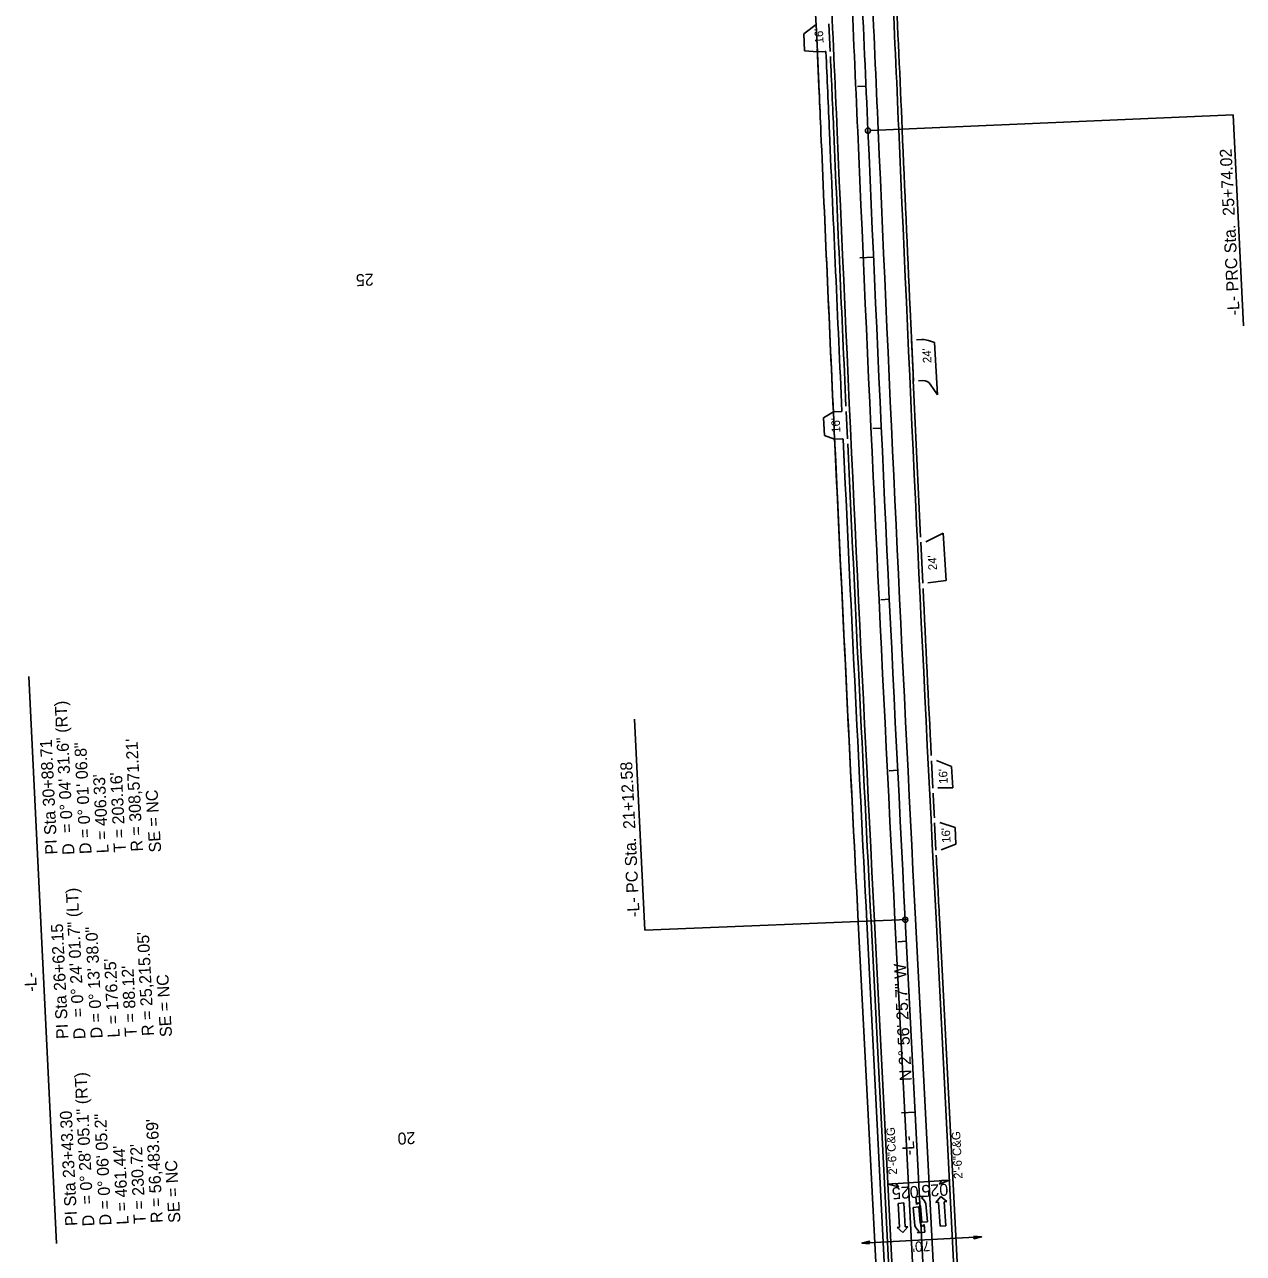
# Model space of a CAD drawing. Extents: x 2367848 to 2369479, y 800728 to 808616.
# Drawn here: x 2368386 to 2369098, y 802247 to 802965 of the extents above; entities that cross this region are included whole.
import ezdxf

# ---------------------------------------------------------------- set-up
doc = ezdxf.new("R2010")
doc.units = 0
for name, color, linetype in [('Prop Conc 2ft 6in Curb and Gutter', 7, 'Continuous'), ('Prop Conc 4in Sidewalk', 7, 'Continuous'), ('Prop Conc Drive Radius Type', 7, 'Continuous'), ('Prop Conc Driveway', 7, 'Continuous'), ('Prop Dimension', 7, 'Continuous'), ('Prop EOT', 7, 'Continuous'), ('Prop Horizontal Alignment', 7, 'Continuous'), ('Prop Horizontal Alignment Curve and Spiral Data', 7, 'Continuous'), ('Prop Horizontal Alignment Direction Label', 7, 'Continuous'), ('Prop Horizontal Alignment Station Label', 7, 'Continuous'), ('Prop Horizontal Alignment Tick Label', 7, 'Continuous'), ('Prop Horizontal Alignment Tick Large', 7, 'Continuous'), ('Prop Horizontal Alignment Tick Small', 7, 'Continuous'), ('Prop Lane Arrow CELL', 7, 'Continuous'), ('Prop Lane Lines', 7, 'Continuous'), ('Prop Shade Light', 7, 'Continuous'), ('Prop Superelevation  Arrow CELL', 7, 'Continuous'), ('Prop Superelevation Label', 7, 'Continuous'), ('Prop Terminator CELL', 7, 'Continuous')]:
    doc.layers.add(name, color=color, linetype=linetype)

msp = doc.modelspace()

# ---------------------------------------------------------------- linework, layer by layer
at = {"layer": 'Prop Conc 2ft 6in Curb and Gutter'}
for p, q in [((2368900.11, 802064.22), (2368880.75, 802441.11)), ((2368933.42, 802195.49), (2368920.7, 802443.16))]:
    msp.add_line(p, q, dxfattribs=at)
for centre, radius, start, end in [((2343687.36, 801815.32), 25235.05, 2.472411, 2.872893), ((2343687.36, 801815.32), 25195.05, 2.472411, 2.572986), ((2425310.05, 805339.67), 56503.69, 182.472411, 182.634937), ((2425310.05, 805339.67), 56463.69, 182.472411, 182.57923), ((2425310.05, 805339.67), 56463.69, 182.57923, 182.714413), ((2425310.05, 805339.67), 56503.69, 182.657207, 182.940485), ((2425310.05, 805339.67), 56463.69, 182.744855, 182.844086), ((2425310.05, 805339.67), 56463.69, 182.866413, 182.880976), ((2425310.05, 805339.67), 56463.69, 182.9033, 182.940485)]:
    msp.add_arc(centre, radius, start, end, dxfattribs=at)
at = {"layer": 'Prop Conc 4in Sidewalk'}
for p, q in [((2368892.58, 802064.58), (2368873.26, 802440.72)), ((2368897.6, 802064.34), (2368878.26, 802440.98))]:
    msp.add_line(p, q, dxfattribs=at)
for centre, radius, start, end in [((2343687.36, 801815.32), 25187.55, 2.614684, 2.872893), ((2343687.36, 801815.32), 25187.55, 2.472411, 2.583481), ((2368854, 802946.23), 3.01, 82.7914, 92.37863), ((2343687.36, 801815.32), 25192.55, 2.472411, 2.579707), ((2425310.05, 805339.67), 56511.19, 182.472411, 182.638782), ((2425310.05, 805339.67), 56506.19, 182.472411, 182.637937), ((2368863.1, 802741.94), 3, 272.68387, 282.26278), ((2425310.05, 805339.67), 56511.19, 182.652485, 182.940485), ((2368864.11, 802719.95), 3.01, 82.87062, 92.4209), ((2425108.22, 805329.81), 56304.12, 182.653736, 182.941)]:
    msp.add_arc(centre, radius, start, end, dxfattribs=at)
at = {"layer": 'Prop Conc Drive Radius Type'}
for p, q in [((2368856.87, 802949.38), (2368856.15, 802965.36)), ((2368904.38, 802780.8), (2368905.46, 802756.82)), ((2368866.97, 802723.1), (2368866.24, 802739.08)), ((2368909.85, 802662.68), (2368911, 802638.71)), ((2368916.05, 802535.04), (2368916.85, 802519.06)), ((2368917.86, 802498.73), (2368918.66, 802482.75))]:
    msp.add_line(p, q, dxfattribs=at)
at = {"layer": 'Prop Conc Driveway'}
for p, q in [((2368849.38, 802949.03), (2368848.66, 802965.01)), ((2368849.38, 802949.04), (2368853.88, 802949.24)), ((2368858.74, 802738.73), (2368863.24, 802738.94)), ((2368859.48, 802722.75), (2368858.74, 802738.74)), ((2368859.48, 802722.75), (2368863.98, 802722.96))]:
    msp.add_line(p, q, dxfattribs=at)
at = {"layer": 'Prop Dimension'}
msp.add_line((2368875.38, 802253.24), (2368945.29, 802256.83), dxfattribs=at)
at = {"layer": 'Prop EOT'}
for p, q in [((2368841.46, 802959.63), (2368848.66, 802965.01)), ((2368841.9, 802949.7), (2368841.46, 802959.63)), ((2368849.38, 802949.03), (2368841.9, 802949.7)), ((2368910.51, 802781.07), (2368907.38, 802780.93)), ((2368917.76, 802779.25), (2368914.38, 802780.48)), ((2368919.63, 802748.74), (2368917.76, 802779.34)), ((2368911.01, 802757.07), (2368908.45, 802756.95)), ((2368919.63, 802748.74), (2368915.35, 802754.92)), ((2368852.97, 802735.31), (2368858.74, 802738.74)), ((2368853.63, 802725.06), (2368852.97, 802735.31)), ((2368859.48, 802722.75), (2368853.63, 802725.06)), ((2368912.85, 802662.82), (2368922.79, 802667.91)), ((2368922.79, 802667.91), (2368924.65, 802640.34)), ((2368913.99, 802638.85), (2368924.65, 802640.34)), ((2368927.83, 802531.65), (2368919.04, 802535.19)), ((2368928.53, 802519.18), (2368927.83, 802531.65)), ((2368919.85, 802519.21), (2368928.53, 802519.18)), ((2368929.83, 802495.98), (2368920.85, 802498.88)), ((2368930.37, 802486.36), (2368929.83, 802495.98)), ((2368921.66, 802482.9), (2368930.37, 802486.36)), ((2368902.12, 802064.13), (2368882.75, 802441.21)), ((2368931.42, 802195.39), (2368918.7, 802443.06))]:
    msp.add_line(p, q, dxfattribs=at)
for centre, radius, start, end in [((2343687.36, 801815.32), 25233.05, 2.472411, 2.872893), ((2343687.36, 801815.32), 25197.05, 2.472411, 2.872893), ((2425310.05, 805339.67), 56501.69, 182.472411, 182.940485), ((2425310.05, 805339.67), 56465.69, 182.472411, 182.940485), ((2368910.96, 802771.08), 10, 70.0247, 92.59747), ((2368911.24, 802752.08), 5, 34.68901, 92.59747)]:
    msp.add_arc(centre, radius, start, end, dxfattribs=at)
at = {"layer": 'Prop Horizontal Alignment'}
msp.add_line((2368929.17, 801888.4), (2368900.73, 802442.14), dxfattribs=at)
for centre, radius, start, end in [((2343687.36, 801815.32), 25215.05, 2.472411, 2.872893), ((2425310.05, 805339.67), 56483.69, 182.472411, 182.940485)]:
    msp.add_arc(centre, radius, start, end, dxfattribs=at)
at = {"layer": 'Prop Horizontal Alignment Station Label'}
for p, q in [((2368880.44, 802903.12), (2369092.3, 802912.27)), ((2369098.31, 802789.04), (2369092.3, 802912.27)), ((2368404.8, 802252.99), (2368388.64, 802584.25)), ((2368748.6, 802436.01), (2368742.59, 802559.24)), ((2368902.22, 802442.21), (2368748.6, 802436.01))]:
    msp.add_line(p, q, dxfattribs=at)
for centre in [(2368878.94, 802903.06), (2368878.94, 802903.06), (2368900.73, 802442.14), (2368900.73, 802442.14)]:
    msp.add_circle(centre, 1.5, dxfattribs=at)
at = {"layer": 'Prop Horizontal Alignment Tick Large'}
for p, q in [((2368882.18, 802829.11), (2368874.19, 802828.75)), ((2368882.18, 802829.11), (2368874.19, 802828.75)), ((2368906.5, 802329.7), (2368898.51, 802329.29)), ((2368906.5, 802329.7), (2368898.51, 802329.29))]:
    msp.add_line(p, q, dxfattribs=at)
at = {"layer": 'Prop Horizontal Alignment Tick Small'}
for p, q in [((2368877.8, 802929.01), (2368872.81, 802928.79)), ((2368877.8, 802929.01), (2368872.81, 802928.79)), ((2368886.71, 802729.21), (2368881.72, 802728.98)), ((2368886.71, 802729.21), (2368881.72, 802728.98)), ((2368891.42, 802629.32), (2368886.43, 802629.08)), ((2368891.42, 802629.32), (2368886.43, 802629.08)), ((2368896.31, 802529.44), (2368891.32, 802529.19)), ((2368896.31, 802529.44), (2368891.32, 802529.19)), ((2368901.37, 802429.57), (2368896.38, 802429.31)), ((2368901.37, 802429.57), (2368896.38, 802429.31))]:
    msp.add_line(p, q, dxfattribs=at)
at = {"layer": 'Prop Lane Arrow CELL'}
for p, q in [((2368896.55, 802276.46), (2368899.84, 802276.68)), ((2368897.46, 802262.49), (2368896.55, 802276.46)), ((2368899.84, 802276.68), (2368900.75, 802262.71)), ((2368908.68, 802274.41), (2368905.4, 802274.1)), ((2368911.27, 802280.67), (2368906.84, 802280.26)), ((2368906.84, 802280.26), (2368907.25, 802275.78)), ((2368907.25, 802275.78), (2368908.2, 802276.92)), ((2368909.52, 802265.3), (2368908.68, 802274.41)), ((2368909.57, 802274.54), (2368910.41, 802265.43)), ((2368910.32, 802279.48), (2368911.27, 802280.67)), ((2368913.7, 802265.73), (2368912.73, 802276.24)), ((2368918.65, 802277.06), (2368921.54, 802280.41)), ((2368920.15, 802277.16), (2368918.65, 802277.06)), ((2368921.06, 802263.19), (2368920.15, 802277.16)), ((2368921.54, 802280.41), (2368924.94, 802277.47)), ((2368924.94, 802277.47), (2368923.44, 802277.37)), ((2368923.44, 802277.37), (2368924.36, 802263.4)), ((2368905.4, 802274.1), (2368906.36, 802263.6)), ((2368895.96, 802262.4), (2368897.46, 802262.49)), ((2368899.36, 802259.46), (2368895.96, 802262.4)), ((2368902.25, 802262.81), (2368899.36, 802259.46)), ((2368900.75, 802262.71), (2368902.25, 802262.81)), ((2368908.77, 802260.36), (2368907.82, 802259.21)), ((2368910.41, 802265.43), (2368913.7, 802265.73)), ((2368911.85, 802264.05), (2368910.9, 802262.91)), ((2368912.21, 802259.57), (2368911.85, 802264.05)), ((2368924.36, 802263.4), (2368921.06, 802263.19)), ((2368907.82, 802259.21), (2368912.21, 802259.57))]:
    msp.add_line(p, q, dxfattribs=at)
for centre, radius, start, end in [((2368906.3, 802274.26), 3.27, 5.25902, 54.91719), ((2368907.62, 802274.98), 5.25, 13.93509, 59.24678), ((2368911.44, 802264.86), 5.25, 193.93509, 239.24678), ((2368912.77, 802265.58), 3.27, 185.25902, 234.91719)]:
    msp.add_arc(centre, radius, start, end, dxfattribs=at)
at = {"layer": 'Prop Lane Lines'}
for p, q in [((2368921.54, 801919.93), (2368894.73, 802441.83)), ((2368933.53, 801920.55), (2368906.72, 802442.44))]:
    msp.add_line(p, q, dxfattribs=at)
for centre, radius, start, end in [((2343687.36, 801815.32), 25209.05, 2.472411, 2.872893), ((2343687.36, 801815.32), 25221.05, 2.472411, 2.872893), ((2425310.05, 805339.67), 56489.69, 182.472411, 182.940485), ((2425310.05, 805339.67), 56477.69, 182.472411, 182.940485)]:
    msp.add_arc(centre, radius, start, end, dxfattribs=at)
at = {"layer": 'Prop Shade Light'}
for p, q in [((2368853.88, 802949.24), (2368849.38, 802949.04)), ((2368858.74, 802738.73), (2368863.24, 802738.94)), ((2368863.98, 802722.96), (2368859.48, 802722.75)), ((2368873.26, 802440.72), (2368892.58, 802064.58)), ((2368897.6, 802064.34), (2368878.26, 802440.98))]:
    msp.add_line(p, q, dxfattribs=at)
for points in [[(2368858.74, 802738.73), (2368858.74, 802738.73)], [(2368859.48, 802722.75), (2368859.48, 802722.75)]]:
    msp.add_lwpolyline(points, dxfattribs=at)
for centre, radius, start, end in [((2343687.36, 801815.32), 25187.55, 2.472411, 2.579803), ((2368854, 802946.23), 3.01, 82.7914, 92.37863), ((2343687.36, 801815.32), 25192.55, 2.472411, 2.579707), ((2425310.05, 805339.67), 56511.19, 182.472411, 182.63798), ((2425310.05, 805339.67), 56506.19, 182.472411, 182.637937), ((2368863.1, 802741.94), 3, 272.68387, 282.26278), ((2425310.05, 805339.67), 56511.19, 182.654203, 182.940485), ((2368864.11, 802719.95), 3.01, 82.87062, 92.4209), ((2425108.22, 805329.81), 56304.12, 182.653736, 182.941)]:
    msp.add_arc(centre, radius, start, end, dxfattribs=at)
at = {"layer": 'Prop Superelevation  Arrow CELL'}
for p, q in [((2368914.58, 802289.32), (2368890.63, 802287.76)), ((2368902.61, 802288.54), (2368926.56, 802290.1))]:
    msp.add_line(p, q, dxfattribs=at)
for points in [[(2368926.56, 802290.1), (2368920.7, 802287.72), (2368921.94, 802289.8)], [(2368890.63, 802287.76), (2368896.75, 802286.16), (2368895.25, 802288.06)]]:
    msp.add_lwpolyline(points, close=True, dxfattribs=at)
at = {"layer": 'Prop Terminator CELL'}
for points in [[(2368879.92, 802252.73), (2368875.38, 802253.24), (2368879.85, 802254.31), (2368879.33, 802253.47)], [(2368940.75, 802257.33), (2368945.29, 802256.83), (2368940.82, 802255.76), (2368941.35, 802256.59)]]:
    msp.add_lwpolyline(points, close=True, dxfattribs=at)

# ---------------------------------------------------------------- texts
at = {"layer": 'Prop Dimension'}
for s, height, rotation, p in [("16'", 5, 92.59666, (2368853.02, 802954.12)), ("24'", 5, 92.73439, (2368916.09, 802767.41)), ("16'", 5, 92.64924, (2368862.83, 802726.68)), ("24'", 5, 92.73439, (2368919.27, 802646.44)), ("16'", 5, 92.85996, (2368925.58, 802521.64)), ("16'", 5, 92.89162, (2368927.23, 802487.18)), ('2\'-6"C&G', 5, 92.94048, (2368895.97, 802293.37)), ('2\'-6"C&G', 5, 92.94048, (2368934.22, 802290.93)), ("70'", 6, 183.45855, (2368915.12, 802254.61))]:
    msp.add_text(s, height=height, rotation=rotation, dxfattribs=at).set_placement(p)
at = {"layer": 'Prop Horizontal Alignment Curve and Spiral Data'}
for s, rotation, p in [('= 0%%d 04\' 31.6" (RT)', 92.79291, (2368414.46, 802493)), ('PI Sta 30+88.71', 92.79291, (2368405.36, 802480.37)), ("R = 308,571.21'", 92.79291, (2368455.34, 802482.13)), ('D = 0%%d 01\' 06.8"', 92.79291, (2368425.37, 802480.67)), ("L = 406.33'", 92.79291, (2368435.36, 802481.15)), ("T = 203.16'", 92.79291, (2368445.35, 802481.64)), ('SE = NC', 93.40304, (2368466.03, 802481.69)), ('D', 92.79291, (2368415.38, 802480.18)), ('= 0%%d 24\' 01.7" (LT)', 92.79291, (2368420.91, 802385.31)), ('PI Sta 26+62.15', 92.79291, (2368411.81, 802372.68)), ('D = 0%%d 13\' 38.0"', 92.79291, (2368431.81, 802372.98)), ("R = 25,215.05'", 92.79291, (2368461.78, 802374.44)), ("L = 176.25'", 92.79291, (2368441.8, 802373.47)), ('-L-', 92.79291, (2368393.4, 802400.23)), ("T = 88.12'", 92.79291, (2368451.79, 802373.96)), ('SE = NC', 93.40304, (2368472.35, 802373.86)), ('D', 92.79291, (2368421.83, 802372.49)), ('= 0%%d 28\' 05.1" (RT)', 92.79291, (2368426.11, 802276.04)), ('PI Sta 23+43.30', 92.79291, (2368417.01, 802263.41)), ('D = 0%%d 06\' 05.2"', 92.79291, (2368437.02, 802263.71)), ("R = 56,483.69'", 92.79291, (2368466.98, 802265.17)), ("T = 230.72'", 92.79291, (2368457, 802264.68)), ("L = 461.44'", 92.79291, (2368447.01, 802264.19)), ('SE = NC', 93.40304, (2368477.32, 802265.29)), ('D', 92.79291, (2368427.03, 802263.22))]:
    msp.add_text(s, height=7, rotation=rotation, dxfattribs=at).set_placement(p)
at = {"layer": 'Prop Horizontal Alignment Direction Label'}
msp.add_text('N 2%%d 56\' 25.7" W', height=7, rotation=92.94048, dxfattribs=at).set_placement((2368904.54, 802348.08))
at = {"layer": 'Prop Horizontal Alignment Station Label'}
for s, rotation, p in [('-L- PRC Sta.  25+74.02', 92.79291, (2369096.14, 802795.27)), ('-L- PC Sta.  21+12.58', 92.79291, (2368745.57, 802443.91)), ('-L-', 92.94048, (2368906.23, 802304.69))]:
    msp.add_text(s, height=7, rotation=rotation, dxfattribs=at).set_placement(p)
at = {"layer": 'Prop Horizontal Alignment Tick Label'}
for s, rotation, p in [('25', 182.5475, (2368590.02, 802819.61)), ('20', 182.94048, (2368614.33, 802318.2))]:
    msp.add_text(s, height=7, rotation=rotation, dxfattribs=at).set_placement(p)
at = {"layer": 'Prop Superelevation Label'}
for p in [(2368908.31, 802286.75), (2368925.58, 802288.06)]:
    msp.add_text('025', height=7, rotation=183.72834, dxfattribs=at).set_placement(p)

doc.saveas('drawing.dxf')
